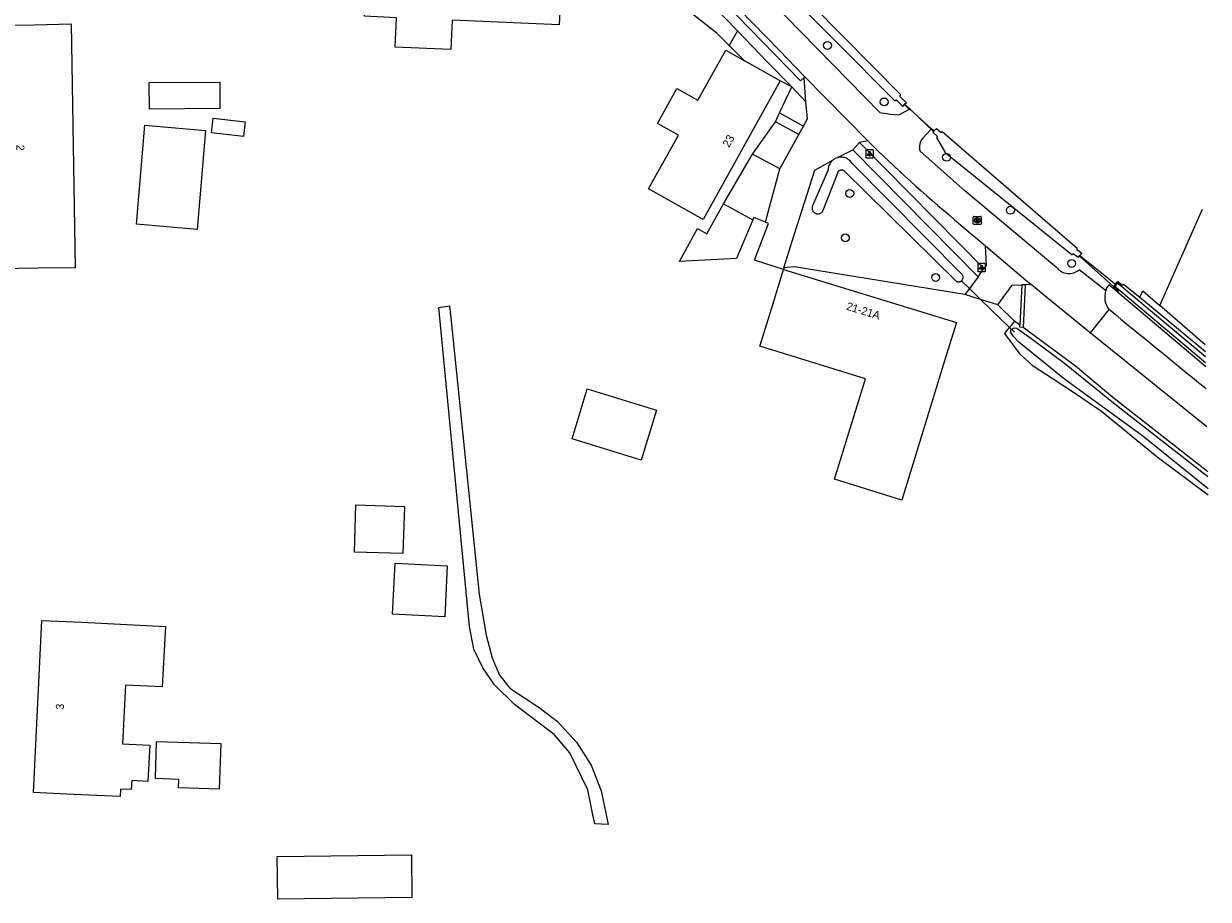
# Model space of a CAD drawing. Extents: x 163863 to 164644, y 379566 to 382155.
# Drawn here: x 164457.9 to 164606, y 381489.4 to 381598.9 of the extents above; entities that cross this region are included whole.
import ezdxf

# ---------------------------------------------------------------- set-up
doc = ezdxf.new("R2010")
doc.units = 0
for name, color, linetype in [('IMGEO_Berm_groen', 7, 'Continuous'), ('IMGEO_Boom', 7, 'Continuous'), ('IMGEO_Duiker', 7, 'Continuous'), ('IMGEO_Erf', 7, 'Continuous'), ('IMGEO_Fietspad_gesloten', 7, 'Continuous'), ('IMGEO_Fietspad_open', 7, 'Continuous'), ('IMGEO_Grasland_agrarisch', 7, 'Continuous'), ('IMGEO_Grasland_overig', 7, 'Continuous'), ('IMGEO_Groenvoorziening', 7, 'Continuous'), ('IMGEO_Lichtpunt', 7, 'Continuous'), ('IMGEO_Pand', 7, 'Continuous'), ('IMGEO_Pand_nummerreeks', 7, 'Continuous'), ('IMGEO_Rijbaan_lokaal_gesloten', 7, 'Continuous'), ('IMGEO_Rioolput', 7, 'Continuous'), ('IMGEO_Sloot', 7, 'Continuous'), ('IMGEO_Voetpad_open', 7, 'Continuous'), ('IMGEO_Waterloop', 7, 'Continuous')]:
    doc.layers.add(name, color=color, linetype=linetype)

msp = doc.modelspace()

# ---------------------------------------------------------------- linework, layer by layer
at = {"layer": 'IMGEO_Berm_groen'}
for points in [[(164583.12, 381566.25), (164582.86, 381560.9)], [(164594.64, 381565.35), (164593.85, 381566), (164593.54, 381566.25)], [(164594.64, 381565.35), (164605.67, 381556.02)], [(164605.93, 381542.85), (164605.72, 381543.02), (164594.05, 381552.16), (164589.38, 381556.06), (164582.86, 381560.9)]]:
    msp.add_lwpolyline(points, dxfattribs=at)
msp.add_arc((164595.65, 381564.72), 2.6, 143.9872, 162.7012, dxfattribs=at)
at = {"layer": 'IMGEO_Boom'}
for centre in [(164558.39, 381596.16), (164565.48, 381589.1), (164573.28, 381582.18), (164561.18, 381577.65), (164581.26, 381575.56), (164560.63, 381572.11), (164588.91, 381568.91), (164571.91, 381567.16)]:
    msp.add_circle(centre, 0.489, dxfattribs=at)
at = {"layer": 'IMGEO_Duiker'}
for points in [[(164571.59, 381585.44), (164568.07, 381588.81)], [(164594.15, 381566.04), (164589.89, 381569.83)], [(164575.14, 381566.73), (164576.13, 381565.77), (164577.54, 381564.4), (164581.14, 381560.91), (164581.75, 381560.31)]]:
    msp.add_lwpolyline(points, dxfattribs=at)
at = {"layer": 'IMGEO_Erf'}
for points in [[(164594.4, 381566.34), (164594.67, 381566.67), (164595.28, 381566.18), (164595.4, 381566.34), (164597.42, 381564.68)], [(164581.14, 381560.91), (164577.54, 381564.4)], [(164605.99, 381539.95), (164599.61, 381544.71), (164592.65, 381550.4), (164589.01, 381552.86), (164586.47, 381554.51), (164584.12, 381556.08), (164582.49, 381557.58), (164581.54, 381558.87), (164580.56, 381560.16), (164581.14, 381560.91)], [(164581.75, 381561.71), (164581.14, 381560.91)]]:
    msp.add_lwpolyline(points, dxfattribs=at)
at = {"layer": 'IMGEO_Fietspad_gesloten'}
msp.add_lwpolyline([(164605.82, 381548.49), (164605.61, 381548.66), (164591.23, 381560.25)], dxfattribs=at)
for centre, radius, start, end in [((165748.84, 382966.68), 1817.81, 230.54157, 231.02719), ((165756.78, 382976.73), 1830.63, 231.0317, 231.04013)]:
    msp.add_arc(centre, radius, start, end, dxfattribs=at)
at = {"layer": 'IMGEO_Fietspad_open'}
for points in [[(164537.57, 381607.88), (164547.15, 381597.97)], [(164555.48, 381592.17), (164555.02, 381591.73), (164551.82, 381595.01), (164539.43, 381607.77)], [(164547.15, 381597.97), (164550.86, 381594.13), (164553.92, 381590.97)], [(164555.7, 381589.13), (164555.48, 381592.17)], [(164555.7, 381589.13), (164553.92, 381590.97)], [(164562.4, 381584.01), (164561.55, 381583.1)], [(164561.55, 381583.1), (164577.23, 381567.25)], [(164577.94, 381568.26), (164562.4, 381584.01)], [(164577.23, 381567.25), (164577.94, 381568.26)]]:
    msp.add_lwpolyline(points, dxfattribs=at)
at = {"layer": 'IMGEO_Grasland_agrarisch'}
msp.add_lwpolyline([(164599.93, 381563.65), (164605.28, 381575.7)], dxfattribs=at)
at = {"layer": 'IMGEO_Grasland_overig'}
for points in [[(164582.68, 381566.23), (164582.45, 381561.2)], [(164597.42, 381564.68), (164597.79, 381565.49), (164599.93, 381563.65)], [(164597.42, 381564.68), (164605.63, 381557.9)], [(164605.62, 381558.73), (164599.93, 381563.65)], [(164582.86, 381560.9), (164582.43, 381560.95), (164582.45, 381561.2)]]:
    msp.add_lwpolyline(points, dxfattribs=at)
at = {"layer": 'IMGEO_Groenvoorziening'}
for points in [[(164546.1, 381596.15), (164544.61, 381597.64), (164538.75, 381602.33), (164529.28, 381606.81), (164529.21, 381608.09), (164529.15, 381608.49)], [(164547.15, 381597.97), (164546.1, 381596.15)], [(164548.03, 381594.24), (164546.1, 381596.15)], [(164553.92, 381590.97), (164552.48, 381591.73)], [(164552.41, 381587.73), (164553.92, 381590.97)], [(164568.04, 381588.78), (164568.68, 381588.2)], [(164549.02, 381582.57), (164551.9, 381586.62)], [(164571.4, 381585.74), (164571.77, 381585.53)], [(164589.95, 381569.92), (164592.85, 381567.59), (164594.4, 381566.34)], [(164575.56, 381565.01), (164554.24, 381568.48), (164552.95, 381568.37)], [(164594.4, 381566.34), (164594.14, 381566.02), (164594.76, 381565.49), (164594.64, 381565.35)], [(164581.75, 381561.71), (164579.68, 381563.74)], [(164582.45, 381561.2), (164581.75, 381561.71)]]:
    msp.add_lwpolyline(points, dxfattribs=at)
at = {"layer": 'IMGEO_Lichtpunt'}
for p, q in [((164563.17, 381583.02), (164563.17, 381582.21)), ((164563.17, 381583.02), (164563.17, 381582.21)), ((164564.07, 381583.11), (164563.26, 381583.11)), ((164564.07, 381583.11), (164563.26, 381583.11)), ((164564.16, 381582.21), (164564.16, 381583.02)), ((164564.16, 381582.21), (164564.16, 381583.02)), ((164563.26, 381582.12), (164564.07, 381582.12)), ((164563.26, 381582.12), (164564.07, 381582.12)), ((164577.17, 381568.81), (164577.17, 381568)), ((164577.17, 381568.81), (164577.17, 381568)), ((164578.07, 381568.9), (164577.26, 381568.9)), ((164578.07, 381568.9), (164577.26, 381568.9)), ((164577.26, 381567.91), (164578.07, 381567.91)), ((164577.26, 381567.91), (164578.07, 381567.91)), ((164578.16, 381568), (164578.16, 381568.81)), ((164578.16, 381568), (164578.16, 381568.81))]:
    msp.add_line(p, q, dxfattribs=at)
for points in [[(164563.54, 381582.68), (164563.58, 381582.65), (164563.39, 381582.39), (164563.35, 381582.42), (164563.54, 381582.68)], [(164563.64, 381582.63), (164563.69, 381582.63), (164563.69, 381582.31), (164563.64, 381582.31), (164563.64, 381582.63)], [(164563.75, 381582.65), (164563.79, 381582.68), (164563.98, 381582.42), (164563.94, 381582.39), (164563.75, 381582.65)], [(164577.54, 381568.47), (164577.58, 381568.44), (164577.39, 381568.18), (164577.35, 381568.21), (164577.54, 381568.47)], [(164577.64, 381568.42), (164577.69, 381568.42), (164577.69, 381568.1), (164577.64, 381568.1), (164577.64, 381568.42)], [(164577.75, 381568.44), (164577.79, 381568.47), (164577.98, 381568.21), (164577.94, 381568.18), (164577.75, 381568.44)]]:
    msp.add_lwpolyline(points, dxfattribs=at)
for centre in [(164563.67, 381582.82), (164577.67, 381568.61)]:
    msp.add_circle(centre, 0.0994, dxfattribs=at)
for centre, start, end in [((164563.26, 381583.02), 90, 180), ((164563.26, 381583.02), 90, 180), ((164564.07, 381583.02), 0, 90), ((164564.07, 381583.02), 0, 90), ((164563.26, 381582.21), 180, 270), ((164563.26, 381582.21), 180, 270), ((164564.07, 381582.21), 270, 0), ((164564.07, 381582.21), 270, 360), ((164577.26, 381568.81), 90, 180), ((164577.26, 381568.81), 90, 180), ((164577.26, 381568), 180, 270), ((164577.26, 381568), 180, 270), ((164578.07, 381568.81), 0, 90), ((164578.07, 381568.81), 0, 90), ((164578.07, 381568), 270, 0), ((164578.07, 381568), 270, 360)]:
    msp.add_arc(centre, 0.0946, start, end, dxfattribs=at)
at = {"layer": 'IMGEO_Pand'}
for points in [[(164511.3, 381595.66), (164504.37, 381595.96), (164504.54, 381599.63), (164500.55, 381599.81), (164500.49, 381603.61), (164500.42, 381608.61), (164525.3, 381607.51), (164524.84, 381598.73), (164511.47, 381599.32), (164511.3, 381595.66)], [(164464.35, 381568.37), (164459.74, 381568.3), (164454.74, 381568.22), (164454.24, 381598.65), (164459.24, 381598.75), (164463.87, 381598.84), (164464.35, 381568.37)], [(164552.48, 381591.73), (164542.86, 381574.41), (164536.02, 381578.22), (164539.76, 381584.96), (164537.14, 381586.42), (164539.57, 381590.79), (164542.21, 381589.32), (164545.68, 381595.56), (164548.03, 381594.24)], [(164552.48, 381591.73), (164548.03, 381594.24)], [(164473.64, 381588.21), (164473.62, 381591.54), (164482.43, 381591.58), (164482.45, 381588.26), (164473.64, 381588.21)], [(164481.41, 381585.22), (164481.62, 381587.06), (164485.6, 381586.6), (164485.39, 381584.77), (164481.41, 381585.22)], [(164479.63, 381573.14), (164472.04, 381573.81), (164473.06, 381586.21), (164480.65, 381585.54), (164479.63, 381573.14)], [(164549.06, 381574.35), (164547.04, 381569.53), (164539.88, 381569.16), (164542.16, 381573.27), (164543.33, 381572.62), (164545.41, 381576.38)], [(164545.41, 381576.38), (164549.06, 381574.35)], [(164552.89, 381568.16), (164574.51, 381561.51), (164573.04, 381556.73), (164567.7, 381539.34), (164559.27, 381541.93), (164563.13, 381554.5), (164549.93, 381558.56), (164551.42, 381563.38), (164552.89, 381568.16)], [(164535.12, 381544.34), (164526.48, 381546.98), (164528.38, 381553.22), (164537.02, 381550.59), (164535.12, 381544.34)], [(164505.51, 381538.52), (164505.32, 381532.64), (164499.26, 381532.84), (164499.46, 381538.72), (164505.51, 381538.52)], [(164510.88, 381531.12), (164510.55, 381524.75), (164504.03, 381525.09), (164504.36, 381531.46), (164510.88, 381531.12)], [(164473.46, 381504.17), (164471.43, 381504.27), (164471.38, 381503.14), (164470.04, 381503.2), (164470, 381502.26), (164464.14, 381502.55), (164459.15, 381502.79), (164460.21, 381524.3), (164465.2, 381524.06), (164475.64, 381523.54), (164475.26, 381515.97), (164470.65, 381516.2), (164470.29, 381508.86), (164473.68, 381508.69), (164473.46, 381504.17)], [(164482.36, 381503.18), (164477.29, 381503.36), (164477.33, 381504.41), (164474.39, 381504.51), (164474.55, 381509.16), (164482.56, 381508.89), (164482.36, 381503.18)], [(164506.46, 381489.64), (164489.69, 381489.43), (164489.62, 381494.77), (164506.39, 381494.98), (164506.46, 381489.64)]]:
    msp.add_lwpolyline(points, dxfattribs=at)
at = {"layer": 'IMGEO_Rijbaan_lokaal_gesloten'}
for points in [[(164568.68, 381588.2), (164567.28, 381587.44), (164566.26, 381587.51), (164564.98, 381587.75), (164543.31, 381609.9), (164529.3, 381624.66), (164528.86, 381625.54)], [(164540.55, 381607.69), (164552.4, 381595.54), (164555.45, 381592.38)], [(164555.45, 381592.38), (164563.42, 381584.23)], [(164568.68, 381588.2), (164571.4, 381585.74)], [(164570.33, 381584.58), (164571.4, 381585.74)], [(164587.08, 381568.35), (164575.56, 381577.97), (164569.96, 381582.95)], [(164574.29, 381574.37), (164578.14, 381571.13)], [(164578.14, 381571.13), (164583.14, 381566.87), (164583.86, 381566.28)], [(164593.16, 381565.49), (164593.09, 381565.55), (164589.86, 381568.1)], [(164591.23, 381560.25), (164585.37, 381565.03), (164583.86, 381566.28)], [(164593.08, 381564.27), (164593.15, 381563.97), (164593.26, 381563.68), (164593.41, 381563.42), (164593.58, 381563.17)], [(164593.58, 381563.17), (164591.23, 381560.25)]]:
    msp.add_lwpolyline(points, dxfattribs=at)
for centre, radius, start, end in [((164697.78, 381721.44), 192.04, 225.6005, 229.9792), ((164571.58, 381583.44), 1.69, 137.8113, 196.975), ((164588.59, 381569.62), 1.97, 220.0219, 310.0315), ((164595.67, 381564.71), 2.63, 162.7292, 189.8222)]:
    msp.add_arc(centre, radius, start, end, dxfattribs=at)
at = {"layer": 'IMGEO_Rioolput'}
for p, q in [((164576.61, 381573.86), (164576.61, 381574.71)), ((164576.68, 381574.79), (164577.54, 381574.79)), ((164577.54, 381573.79), (164576.68, 381573.79)), ((164577.12, 381574.01), (164577.09, 381574.01)), ((164577.1, 381574.57), (164577.12, 381574.57)), ((164577.61, 381574.71), (164577.61, 381573.86))]:
    msp.add_line(p, q, dxfattribs=at)
for points in [[(164576.61, 381573.86), (164576.61, 381574.71)], [(164576.68, 381574.79), (164577.54, 381574.79)], [(164577.54, 381573.79), (164576.68, 381573.79)], [(164577.2, 381574.48), (164576.94, 381574.49), (164576.94, 381574.09)], [(164576.94, 381574.09), (164577.07, 381574.09), (164577.07, 381574.25), (164577.08, 381574.25)], [(164577.12, 381574.41), (164577.07, 381574.41), (164577.07, 381574.32)], [(164577.07, 381574.32), (164577.12, 381574.32)], [(164577.13, 381574.22), (164577.2, 381574.09), (164577.34, 381574.09), (164577.27, 381574.21)], [(164577.61, 381574.71), (164577.61, 381573.86)]]:
    msp.add_lwpolyline(points, dxfattribs=at)
for centre, radius, start, end in [((164576.68, 381574.71), 0.0765, 91.552, 178.448), ((164576.68, 381574.71), 0.0765, 91.552, 178.448), ((164576.68, 381573.86), 0.0765, 181.552, 268.448), ((164576.68, 381573.86), 0.0765, 181.552, 268.448), ((164577.08, 381574.2), 0.0533, 26.0293, 88.6989), ((164577.13, 381574.31), 0.0964, 77.0061, 93.1865), ((164577.11, 381574.51), 0.19, 274.7715, 282.9687), ((164577.14, 381574.37), 0.0378, 276.6634, 79.6772), ((164577.2, 381574.37), 0.109, 350.3612, 89.416), ((164577.19, 381574.37), 0.112, 277.5842, 350.9817), ((164577.18, 381574.16), 0.108, 29.5134, 73.7905), ((164577.53, 381574.71), 0.0765, 1.552, 88.448), ((164577.53, 381574.71), 0.0765, 1.552, 88.448), ((164577.53, 381573.86), 0.0765, 271.552, 358.448), ((164577.53, 381573.86), 0.0765, 271.552, 358.448)]:
    msp.add_arc(centre, radius, start, end, dxfattribs=at)
for centre, major_axis, ratio, start_param, end_param in [((164577.1, 381574.29), (-0.387, 0.002), 0.722429, 4.712389, 7.853982), ((164577.12, 381574.29), (-0.39, 0.002), 0.717154, 1.570796, 4.712389)]:
    msp.add_ellipse(centre, major_axis=major_axis, ratio=ratio, start_param=start_param, end_param=end_param, dxfattribs=at)
at = {"layer": 'IMGEO_Sloot'}
for points in [[(164594.33, 381566.04), (164594.67, 381566.43), (164605.65, 381557.26)], [(164605.66, 381556.5), (164594.33, 381566.04)], [(164605.98, 381540.74), (164605.76, 381540.91), (164597.82, 381547.31), (164588.01, 381554.43), (164582.32, 381559.06), (164581.62, 381559.8), (164581.28, 381560.37), (164581.35, 381560.65), (164581.73, 381560.86), (164582.08, 381560.82), (164583.8, 381559.55), (164588.01, 381556.44), (164594.36, 381551.34), (164605.73, 381542.44), (164605.95, 381542.27)]]:
    msp.add_lwpolyline(points, dxfattribs=at)
at = {"layer": 'IMGEO_Voetpad_open'}
for points in [[(164555.45, 381592.38), (164555.48, 381592.17)], [(164555.39, 381586.08), (164555.89, 381586.98), (164555.7, 381589.13)], [(164551.9, 381586.62), (164552.41, 381587.73)], [(164552.41, 381587.73), (164555.39, 381586.08)], [(164554.8, 381585.02), (164551.9, 381586.62)], [(164554.8, 381585.02), (164555.39, 381586.08)], [(164552.46, 381580.72), (164554.8, 381585.02)], [(164563.42, 381584.23), (164562.4, 381584.01)], [(164545.41, 381576.38), (164549.02, 381582.57)], [(164552.46, 381580.72), (164549.02, 381582.57)], [(164559.65, 381582.14), (164561.55, 381583.1)], [(164552.95, 381568.37), (164553.97, 381571.68), (164556.81, 381580.58), (164559.1, 381581.86)], [(164559.65, 381582.14), (164559.55, 381582.1), (164559.42, 381582.05), (164559.29, 381581.99), (164559.18, 381581.91), (164559.1, 381581.86)], [(164550.63, 381574.07), (164551.03, 381575.5), (164552.46, 381580.72)], [(164550.63, 381574.07), (164549.38, 381574.58), (164549.18, 381574.66), (164549.06, 381574.35)], [(164552.89, 381568.16), (164549.26, 381569.31), (164551.01, 381573.92), (164550.63, 381574.07)], [(164577.94, 381568.26), (164578.25, 381568.67), (164578.14, 381571.13)], [(164552.95, 381568.37), (164552.89, 381568.16)], [(164577.23, 381567.25), (164576.13, 381565.77), (164575.56, 381565.01)], [(164583.86, 381566.28), (164583.12, 381566.25)], [(164577.54, 381564.4), (164575.56, 381565.01)], [(164579.68, 381563.74), (164581.47, 381566.18), (164582.68, 381566.23)], [(164583.12, 381566.25), (164582.68, 381566.23)], [(164579.68, 381563.74), (164577.54, 381564.4)]]:
    msp.add_lwpolyline(points, dxfattribs=at)
at = {"layer": 'IMGEO_Waterloop'}
for points in [[(164530.68, 381628.73), (164529.92, 381627.46), (164530.34, 381625.94), (164566.8, 381589.23), (164566.97, 381589.37), (164567.8, 381588.54), (164568.04, 381588.78)], [(164531.45, 381627.87), (164530.94, 381627.08), (164567.56, 381589.98), (164567.41, 381589.82), (164568.26, 381588.99), (164568.04, 381588.78)], [(164571.77, 381585.53), (164571.56, 381585.31), (164572.14, 381584.79), (164572.03, 381584.64), (164573.09, 381582.77), (164588.96, 381570), (164589.08, 381570.16), (164589.76, 381569.68), (164589.95, 381569.92)], [(164571.77, 381585.53), (164572.01, 381585.78), (164572.6, 381585.28), (164572.74, 381585.42), (164589.62, 381570.83), (164589.5, 381570.69), (164590.18, 381570.21), (164589.95, 381569.92)], [(164559.1, 381581.86), (164559.07, 381581.83), (164558.96, 381581.74), (164558.87, 381581.64), (164558.78, 381581.53), (164558.71, 381581.41), (164558.64, 381581.29), (164558.58, 381581.16), (164558.54, 381581.03), (164558.51, 381580.9), (164558.49, 381580.76), (164558.48, 381580.62), (164556.53, 381576.11), (164556.51, 381576.05), (164556.49, 381575.99), (164556.48, 381575.93), (164556.47, 381575.87), (164556.47, 381575.8), (164556.48, 381575.74), (164556.49, 381575.68), (164556.5, 381575.62), (164556.52, 381575.56), (164556.55, 381575.5), (164556.58, 381575.44), (164556.62, 381575.39), (164556.66, 381575.34), (164556.7, 381575.3), (164556.75, 381575.26), (164556.8, 381575.22), (164556.86, 381575.19), (164556.92, 381575.16), (164556.98, 381575.14), (164557.04, 381575.12), (164557.1, 381575.11), (164557.16, 381575.11), (164557.23, 381575.11), (164557.29, 381575.12), (164557.35, 381575.13), (164557.41, 381575.15), (164557.47, 381575.17), (164557.53, 381575.2), (164557.58, 381575.23), (164557.63, 381575.27), (164557.68, 381575.31), (164557.73, 381575.35), (164557.77, 381575.4), (164557.8, 381575.45), (164557.83, 381575.51), (164557.86, 381575.57), (164559.66, 381580.12), (164559.66, 381580.17), (164559.67, 381580.21), (164559.68, 381580.25), (164559.69, 381580.29), (164559.71, 381580.33), (164559.73, 381580.37), (164559.75, 381580.4), (164559.77, 381580.44), (164559.8, 381580.47), (164559.83, 381580.5), (164559.87, 381580.52), (164559.9, 381580.54), (164559.94, 381580.57), (164559.98, 381580.58), (164560.02, 381580.59), (164560.06, 381580.6), (164560.1, 381580.61), (164560.14, 381580.61), (164560.19, 381580.61), (164560.23, 381580.6), (164560.27, 381580.6), (164560.31, 381580.58), (164560.35, 381580.57), (164560.39, 381580.55), (164560.42, 381580.53), (164560.46, 381580.5), (164560.49, 381580.47), (164560.52, 381580.44), (164574.42, 381566.75), (164574.45, 381566.72), (164574.49, 381566.7), (164574.54, 381566.67), (164574.58, 381566.65), (164574.63, 381566.64), (164574.68, 381566.63), (164574.72, 381566.62), (164574.77, 381566.62), (164574.82, 381566.62), (164574.87, 381566.62), (164574.92, 381566.63), (164574.96, 381566.64), (164575.01, 381566.66), (164575.05, 381566.68), (164575.1, 381566.71), (164575.14, 381566.73), (164575.17, 381566.77), (164575.21, 381566.8), (164575.24, 381566.84), (164575.27, 381566.88), (164575.29, 381566.93), (164575.32, 381566.97), (164575.33, 381567.02), (164575.34, 381567.07), (164575.35, 381567.12), (164575.36, 381567.17), (164575.35, 381567.22), (164575.35, 381567.27), (164575.34, 381567.32), (164575.32, 381567.37), (164575.3, 381567.42), (164575.28, 381567.46), (164575.26, 381567.51), (164575.23, 381567.54), (164575.19, 381567.58), (164561.47, 381581.4), (164561.39, 381581.52), (164561.31, 381581.63), (164561.22, 381581.73), (164561.11, 381581.82), (164561, 381581.91), (164560.89, 381581.98), (164560.76, 381582.05), (164560.64, 381582.1), (164560.5, 381582.14), (164560.37, 381582.17), (164560.23, 381582.19), (164560.09, 381582.2), (164559.95, 381582.19), (164559.81, 381582.17), (164559.68, 381582.15), (164559.65, 381582.14)], [(164514.87, 381527.59), (164515.72, 381522.45), (164516.49, 381519.63), (164517.39, 381517.44), (164518.7, 381515.83), (164522.34, 381513.39), (164524.64, 381511.65), (164527.01, 381509.09), (164528.84, 381506.21), (164530.09, 381502.98), (164530.72, 381500), (164530.98, 381498.78), (164529.3, 381498.86), (164529.07, 381500), (164528.44, 381503.11), (164526.21, 381507.75), (164524.25, 381510.03), (164519.27, 381513.79), (164516.77, 381516.22), (164515.31, 381518.37), (164514.21, 381520.68), (164513.67, 381523.51), (164509.82, 381563.39), (164511.17, 381563.61), (164511.32, 381562.12), (164514.87, 381527.59)]]:
    msp.add_lwpolyline(points, dxfattribs=at)

# ---------------------------------------------------------------- texts
at = {"layer": 'IMGEO_Pand_nummerreeks'}
for s, rotation, p in [('23', 60.745, (164546.09, 381583.33)), ('2', 270.9487, (164457.01, 381583.75)), ('21-21A', 342.9029, (164560.67, 381563.15)), ('3', 87.189, (164462.94, 381513.11))]:
    msp.add_text(s, height=1, rotation=rotation, dxfattribs=at).set_placement(p)

doc.saveas('drawing.dxf')
